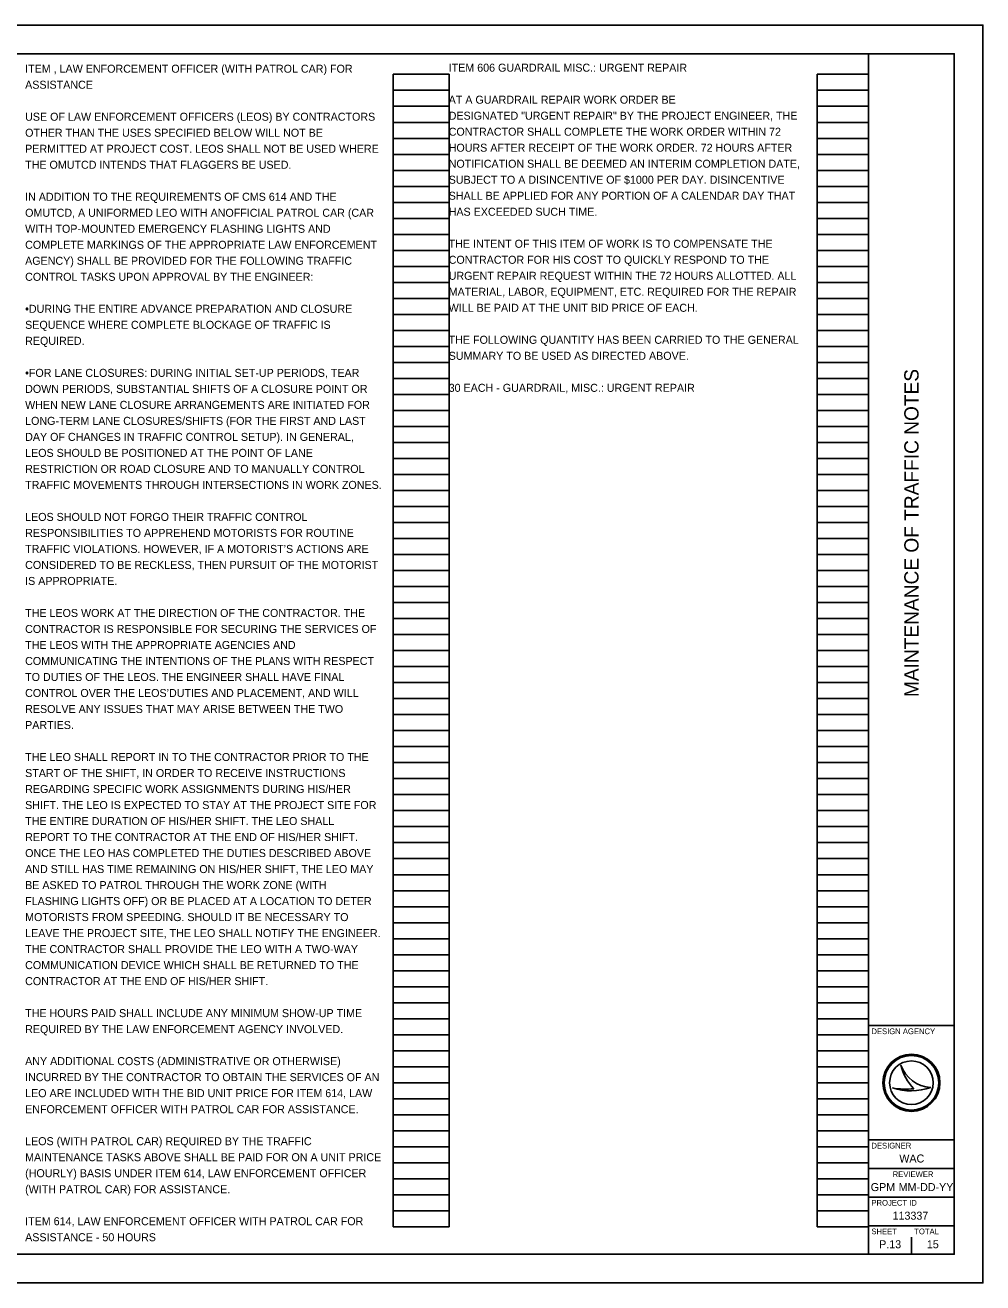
# Model space of a CAD drawing. Extents: x 0 to 34, y 0 to 22.
# Drawn here: x 17.24 to 34, y 0 to 22 of the extents above; entities that cross this region are included whole.
import ezdxf

# ---------------------------------------------------------------- set-up
doc = ezdxf.new("R2010")
doc.units = 0
for name, color, linetype in [('SH_Border', 7, 'Continuous'), ('SH_Cut_Line', 7, 'Continuous'), ('SH_Data', 7, 'Continuous'), ('SH_Text', 7, 'Continuous')]:
    doc.layers.add(name, color=color, linetype=linetype)

msp = doc.modelspace()

# ---------------------------------------------------------------- linework, layer by layer
at = {"layer": 'SH_Border'}
for p, q in [((32, 0.5), (32, 21.5)), ((32, 4.5), (33.5, 4.5)), ((32, 2.5), (33.5, 2.5)), ((32, 2), (33.5, 2)), ((32, 1.5), (33.5, 1.5)), ((32, 1), (33.5, 1))]:
    msp.add_line(p, q, dxfattribs=at)
msp.add_lwpolyline([(1.5, 21.5), (33.5, 21.5), (33.5, 0.5), (1.5, 0.5)], close=True, dxfattribs=at)
at = {"layer": 'SH_Cut_Line'}
msp.add_lwpolyline([(0, 0), (34, 0), (34, 22), (0, 22)], close=True, dxfattribs=at)
at = {"layer": 'SH_Data'}
for p, q in [((23.68, 0.98), (23.68, 21.14)), ((23.68, 21.14), (24.66, 21.14)), ((24.66, 0.98), (24.66, 21.14)), ((31.1, 0.98), (31.1, 21.14)), ((31.1, 21.14), (32, 21.14)), ((32, 0.98), (32, 21.14)), ((23.68, 20.86), (24.66, 20.86)), ((31.1, 20.86), (32, 20.86)), ((23.68, 20.58), (24.66, 20.58)), ((31.1, 20.58), (32, 20.58)), ((23.68, 20.3), (24.66, 20.3)), ((31.1, 20.3), (32, 20.3)), ((23.68, 20.02), (24.66, 20.02)), ((31.1, 20.02), (32, 20.02)), ((23.68, 19.74), (24.66, 19.74)), ((31.1, 19.74), (32, 19.74)), ((23.68, 19.46), (24.66, 19.46)), ((31.1, 19.46), (32, 19.46)), ((23.68, 19.18), (24.66, 19.18)), ((31.1, 19.18), (32, 19.18)), ((23.68, 18.9), (24.66, 18.9)), ((31.1, 18.9), (32, 18.9)), ((23.68, 18.62), (24.66, 18.62)), ((31.1, 18.62), (32, 18.62)), ((23.68, 18.34), (24.66, 18.34)), ((31.1, 18.34), (32, 18.34)), ((23.68, 18.06), (24.66, 18.06)), ((31.1, 18.06), (32, 18.06)), ((23.68, 17.78), (24.66, 17.78)), ((31.1, 17.78), (32, 17.78)), ((23.68, 17.5), (24.66, 17.5)), ((31.1, 17.5), (32, 17.5)), ((23.68, 17.22), (24.66, 17.22)), ((31.1, 17.22), (32, 17.22)), ((23.68, 16.94), (24.66, 16.94)), ((31.1, 16.94), (32, 16.94)), ((23.68, 16.66), (24.66, 16.66)), ((31.1, 16.66), (32, 16.66)), ((23.68, 16.38), (24.66, 16.38)), ((31.1, 16.38), (32, 16.38)), ((23.68, 16.1), (24.66, 16.1)), ((31.1, 16.1), (32, 16.1)), ((23.68, 15.82), (24.66, 15.82)), ((31.1, 15.82), (32, 15.82)), ((23.68, 15.54), (24.66, 15.54)), ((31.1, 15.54), (32, 15.54)), ((23.68, 15.26), (24.66, 15.26)), ((31.1, 15.26), (32, 15.26)), ((23.68, 14.98), (24.66, 14.98)), ((31.1, 14.98), (32, 14.98)), ((23.68, 14.7), (24.66, 14.7)), ((31.1, 14.7), (32, 14.7)), ((23.68, 14.42), (24.66, 14.42)), ((31.1, 14.42), (32, 14.42)), ((23.68, 14.14), (24.66, 14.14)), ((31.1, 14.14), (32, 14.14)), ((23.68, 13.86), (24.66, 13.86)), ((31.1, 13.86), (32, 13.86)), ((23.68, 13.58), (24.66, 13.58)), ((31.1, 13.58), (32, 13.58)), ((23.68, 13.3), (24.66, 13.3)), ((31.1, 13.3), (32, 13.3)), ((23.68, 13.02), (24.66, 13.02)), ((31.1, 13.02), (32, 13.02)), ((23.68, 12.74), (24.66, 12.74)), ((31.1, 12.74), (32, 12.74)), ((23.68, 12.46), (24.66, 12.46)), ((31.1, 12.46), (32, 12.46)), ((23.68, 12.18), (24.66, 12.18)), ((31.1, 12.18), (32, 12.18)), ((23.68, 11.9), (24.66, 11.9)), ((31.1, 11.9), (32, 11.9)), ((23.68, 11.62), (24.66, 11.62)), ((31.1, 11.62), (32, 11.62)), ((23.68, 11.34), (24.66, 11.34)), ((31.1, 11.34), (32, 11.34)), ((23.68, 11.06), (24.66, 11.06)), ((31.1, 11.06), (32, 11.06)), ((23.68, 10.78), (24.66, 10.78)), ((31.1, 10.78), (32, 10.78)), ((23.68, 10.5), (24.66, 10.5)), ((31.1, 10.5), (32, 10.5)), ((23.68, 10.22), (24.66, 10.22)), ((31.1, 10.22), (32, 10.22)), ((23.68, 9.94), (24.66, 9.94)), ((31.1, 9.94), (32, 9.94)), ((23.68, 9.66), (24.66, 9.66)), ((31.1, 9.66), (32, 9.66)), ((23.68, 9.38), (24.66, 9.38)), ((31.1, 9.38), (32, 9.38)), ((23.68, 9.1), (24.66, 9.1)), ((31.1, 9.1), (32, 9.1)), ((23.68, 8.82), (24.66, 8.82)), ((31.1, 8.82), (32, 8.82)), ((23.68, 8.54), (24.66, 8.54)), ((31.1, 8.54), (32, 8.54)), ((23.68, 8.26), (24.66, 8.26)), ((31.1, 8.26), (32, 8.26)), ((23.68, 7.98), (24.66, 7.98)), ((31.1, 7.98), (32, 7.98)), ((23.68, 7.7), (24.66, 7.7)), ((31.1, 7.7), (32, 7.7)), ((23.68, 7.42), (24.66, 7.42)), ((31.1, 7.42), (32, 7.42)), ((23.68, 7.14), (24.66, 7.14)), ((31.1, 7.14), (32, 7.14)), ((23.68, 6.86), (24.66, 6.86)), ((31.1, 6.86), (32, 6.86)), ((23.68, 6.58), (24.66, 6.58)), ((31.1, 6.58), (32, 6.58)), ((23.68, 6.3), (24.66, 6.3)), ((31.1, 6.3), (32, 6.3)), ((23.68, 6.02), (24.66, 6.02)), ((31.1, 6.02), (32, 6.02)), ((23.68, 5.74), (24.66, 5.74)), ((31.1, 5.74), (32, 5.74)), ((23.68, 5.46), (24.66, 5.46)), ((31.1, 5.46), (32, 5.46)), ((23.68, 5.18), (24.66, 5.18)), ((31.1, 5.18), (32, 5.18)), ((23.68, 4.9), (24.66, 4.9)), ((31.1, 4.9), (32, 4.9)), ((23.68, 4.62), (24.66, 4.62)), ((31.1, 4.62), (32, 4.62)), ((23.68, 4.34), (24.66, 4.34)), ((31.1, 4.34), (32, 4.34)), ((23.68, 4.06), (24.66, 4.06)), ((31.1, 4.06), (32, 4.06)), ((23.68, 3.78), (24.66, 3.78)), ((31.1, 3.78), (32, 3.78)), ((32.567, 3.81), (32.567, 3.81)), ((23.68, 3.5), (24.66, 3.5)), ((31.1, 3.5), (32, 3.5)), ((32.417, 3.41), (32.417, 3.41)), ((32.75, 3.5), (32.75, 3.5)), ((33.087, 3.419), (33.087, 3.419)), ((23.68, 3.22), (24.66, 3.22)), ((31.1, 3.22), (32, 3.22)), ((23.68, 2.94), (24.66, 2.94)), ((31.1, 2.94), (32, 2.94)), ((23.68, 2.66), (24.66, 2.66)), ((31.1, 2.66), (32, 2.66)), ((23.68, 2.38), (24.66, 2.38)), ((31.1, 2.38), (32, 2.38)), ((23.68, 2.1), (24.66, 2.1)), ((31.1, 2.1), (32, 2.1)), ((23.68, 1.82), (24.66, 1.82)), ((31.1, 1.82), (32, 1.82)), ((23.68, 1.54), (24.66, 1.54)), ((31.1, 1.54), (32, 1.54)), ((23.68, 1.26), (24.66, 1.26)), ((31.1, 1.26), (32, 1.26)), ((23.68, 0.98), (24.66, 0.98)), ((31.1, 0.98), (32, 0.98)), ((32.375, 0.675), (32.375, 0.675)), ((32.75, 0.5), (32.75, 0.8))]:
    msp.add_line(p, q, dxfattribs=at)
for radius in [0.5, 0.477, 0.477, 0.382]:
    msp.add_circle((32.75, 3.5), radius, dxfattribs=at)
for centre, radius, start, end in [((33.116, 3.998), 0.58, 198.9257, 198.9319), ((33.347, 3.97), 0.796, 191.6379, 191.6421), ((33.116, 3.998), 0.58, 198.9319, 267.1657), ((33.347, 3.97), 0.796, 191.6421, 226.0947), ((32.739, 4.37), 1.013, 251.4576, 290.0832), ((32.648, 4.654), 1.266, 259.4964, 259.4995), ((32.739, 4.37), 1.013, 251.4527, 251.4576), ((32.648, 4.654), 1.266, 259.4995, 276.6672)]:
    msp.add_arc(centre, radius, start, end, dxfattribs=at)

# ---------------------------------------------------------------- texts
msp.add_text('MAINTENANCE OF TRAFFIC NOTES', height=0.25, rotation=90, dxfattribs=at).set_placement((32.875, 10.247))
for s, height, p in [('DESIGN AGENCY', 0.1, (32.05, 4.35)), ('DESIGNER', 0.1, (32.05, 2.35)), ('WAC', 0.14, (32.538, 2.105)), ('REVIEWER', 0.1, (32.422, 1.85)), ('GPM', 0.14, (32.038, 1.605)), ('MM-DD-YY', 0.14, (32.527, 1.605)), ('PROJECT ID', 0.1, (32.05, 1.35)), ('113337', 0.14, (32.42, 1.105)), ('SHEET', 0.1, (32.05, 0.85)), ('TOTAL', 0.1, (32.8, 0.85)), ('P.13', 0.14, (32.185, 0.605)), ('15', 0.14, (33.02, 0.605))]:
    msp.add_text(s, height=height, dxfattribs=at).set_placement(p)
at = {"layer": 'SH_Text'}
for s, p in [('ITEM , LAW ENFORCEMENT OFFICER (WITH PATROL CAR) FOR', (17.24, 21.168)), ('ITEM 606 GUARDRAIL MISC.: URGENT REPAIR', (24.652, 21.186)), ('ASSISTANCE', (17.24, 20.888)), ('AT A GUARDRAIL REPAIR WORK ORDER BE', (24.652, 20.626)), ('USE OF LAW ENFORCEMENT OFFICERS (LEOS) BY CONTRACTORS', (17.24, 20.328)), ('DESIGNATED "URGENT REPAIR" BY THE PROJECT ENGINEER, THE', (24.652, 20.346)), ('OTHER THAN THE USES SPECIFIED BELOW WILL NOT BE', (17.24, 20.048)), ('CONTRACTOR SHALL COMPLETE THE WORK ORDER WITHIN 72', (24.652, 20.066)), ('PERMITTED AT PROJECT COST. LEOS SHALL NOT BE USED WHERE', (17.24, 19.768)), ('HOURS AFTER RECEIPT OF THE WORK ORDER. 72 HOURS AFTER', (24.652, 19.786)), ('THE OMUTCD INTENDS THAT FLAGGERS BE USED.', (17.24, 19.488)), ('NOTIFICATION SHALL BE DEEMED AN INTERIM COMPLETION DATE,', (24.652, 19.506)), ('SUBJECT TO A DISINCENTIVE OF $1000 PER DAY. DISINCENTIVE', (24.652, 19.226)), ('IN ADDITION TO THE REQUIREMENTS OF CMS 614 AND THE', (17.24, 18.928)), ('SHALL BE APPLIED FOR ANY PORTION OF A CALENDAR DAY THAT', (24.652, 18.946)), ('OMUTCD, A UNIFORMED LEO WITH ANOFFICIAL PATROL CAR (CAR', (17.24, 18.648)), ('HAS EXCEEDED SUCH TIME.', (24.652, 18.666)), ('WITH TOP-MOUNTED EMERGENCY FLASHING LIGHTS AND', (17.24, 18.368)), ('COMPLETE MARKINGS OF THE APPROPRIATE LAW ENFORCEMENT', (17.24, 18.088)), ('THE INTENT OF THIS ITEM OF WORK IS TO COMPENSATE THE', (24.652, 18.106)), ('AGENCY) SHALL BE PROVIDED FOR THE FOLLOWING TRAFFIC', (17.24, 17.808)), ('CONTRACTOR FOR HIS COST TO QUICKLY RESPOND TO THE', (24.652, 17.826)), ('CONTROL TASKS UPON APPROVAL BY THE ENGINEER:', (17.24, 17.528)), ('URGENT REPAIR REQUEST WITHIN THE 72 HOURS ALLOTTED. ALL', (24.652, 17.546)), ('MATERIAL, LABOR, EQUIPMENT, ETC. REQUIRED FOR THE REPAIR', (24.652, 17.266)), ('•DURING THE ENTIRE ADVANCE PREPARATION AND CLOSURE', (17.24, 16.968)), ('WILL BE PAID AT THE UNIT BID PRICE OF EACH.', (24.652, 16.986)), ('SEQUENCE WHERE COMPLETE BLOCKAGE OF TRAFFIC IS', (17.24, 16.688)), ('REQUIRED.', (17.24, 16.408)), ('THE FOLLOWING QUANTITY HAS BEEN CARRIED TO THE GENERAL', (24.652, 16.426)), ('SUMMARY TO BE USED AS DIRECTED ABOVE.', (24.652, 16.146)), ('•FOR LANE CLOSURES: DURING INITIAL SET-UP PERIODS, TEAR', (17.24, 15.848)), ('DOWN PERIODS, SUBSTANTIAL SHIFTS OF A CLOSURE POINT OR', (17.24, 15.568)), ('30 EACH - GUARDRAIL, MISC.: URGENT REPAIR', (24.652, 15.586)), ('WHEN NEW LANE CLOSURE ARRANGEMENTS ARE INITIATED FOR', (17.24, 15.288)), ('LONG-TERM LANE CLOSURES/SHIFTS (FOR THE FIRST AND LAST', (17.24, 15.008)), ('DAY OF CHANGES IN TRAFFIC CONTROL SETUP). IN GENERAL,', (17.24, 14.728)), ('LEOS SHOULD BE POSITIONED AT THE POINT OF LANE', (17.24, 14.448)), ('RESTRICTION OR ROAD CLOSURE AND TO MANUALLY CONTROL', (17.24, 14.168)), ('TRAFFIC MOVEMENTS THROUGH INTERSECTIONS IN WORK ZONES.', (17.24, 13.888)), ('LEOS SHOULD NOT FORGO THEIR TRAFFIC CONTROL', (17.24, 13.328)), ('RESPONSIBILITIES TO APPREHEND MOTORISTS FOR ROUTINE', (17.24, 13.048)), ('TRAFFIC VIOLATIONS. HOWEVER, IF A MOTORIST’S ACTIONS ARE', (17.24, 12.768)), ('CONSIDERED TO BE RECKLESS, THEN PURSUIT OF THE MOTORIST', (17.24, 12.488)), ('IS APPROPRIATE.', (17.24, 12.208)), ('THE LEOS WORK AT THE DIRECTION OF THE CONTRACTOR. THE', (17.24, 11.648)), ('CONTRACTOR IS RESPONSIBLE FOR SECURING THE SERVICES OF', (17.24, 11.368)), ('THE LEOS WITH THE APPROPRIATE AGENCIES AND', (17.24, 11.088)), ('COMMUNICATING THE INTENTIONS OF THE PLANS WITH RESPECT', (17.24, 10.808)), ('TO DUTIES OF THE LEOS. THE ENGINEER SHALL HAVE FINAL', (17.24, 10.528)), ('CONTROL OVER THE LEOS’DUTIES AND PLACEMENT, AND WILL', (17.24, 10.248)), ('RESOLVE ANY ISSUES THAT MAY ARISE BETWEEN THE TWO', (17.24, 9.968)), ('PARTIES.', (17.24, 9.688)), ('THE LEO SHALL REPORT IN TO THE CONTRACTOR PRIOR TO THE', (17.24, 9.128)), ('START OF THE SHIFT, IN ORDER TO RECEIVE INSTRUCTIONS', (17.24, 8.848)), ('REGARDING SPECIFIC WORK ASSIGNMENTS DURING HIS/HER', (17.24, 8.568)), ('SHIFT. THE LEO IS EXPECTED TO STAY AT THE PROJECT SITE FOR', (17.24, 8.288)), ('THE ENTIRE DURATION OF HIS/HER SHIFT. THE LEO SHALL', (17.24, 8.008)), ('REPORT TO THE CONTRACTOR AT THE END OF HIS/HER SHIFT.', (17.24, 7.728)), ('ONCE THE LEO HAS COMPLETED THE DUTIES DESCRIBED ABOVE', (17.24, 7.448)), ('AND STILL HAS TIME REMAINING ON HIS/HER SHIFT, THE LEO MAY', (17.24, 7.168)), ('BE ASKED TO PATROL THROUGH THE WORK ZONE (WITH', (17.24, 6.888)), ('FLASHING LIGHTS OFF) OR BE PLACED AT A LOCATION TO DETER', (17.24, 6.608)), ('MOTORISTS FROM SPEEDING. SHOULD IT BE NECESSARY TO', (17.24, 6.328)), ('LEAVE THE PROJECT SITE, THE LEO SHALL NOTIFY THE ENGINEER.', (17.24, 6.048)), ('THE CONTRACTOR SHALL PROVIDE THE LEO WITH A TWO-WAY', (17.24, 5.768)), ('COMMUNICATION DEVICE WHICH SHALL BE RETURNED TO THE', (17.24, 5.488)), ('CONTRACTOR AT THE END OF HIS/HER SHIFT.', (17.24, 5.208)), ('THE HOURS PAID SHALL INCLUDE ANY MINIMUM SHOW-UP TIME', (17.24, 4.648)), ('REQUIRED BY THE LAW ENFORCEMENT AGENCY INVOLVED.', (17.24, 4.368)), ('ANY ADDITIONAL COSTS (ADMINISTRATIVE OR OTHERWISE)', (17.24, 3.808)), ('INCURRED BY THE CONTRACTOR TO OBTAIN THE SERVICES OF AN', (17.24, 3.528)), ('LEO ARE INCLUDED WITH THE BID UNIT PRICE FOR ITEM 614, LAW', (17.24, 3.248)), ('ENFORCEMENT OFFICER WITH PATROL CAR FOR ASSISTANCE.', (17.24, 2.968)), ('LEOS (WITH PATROL CAR) REQUIRED BY THE TRAFFIC', (17.24, 2.408)), ('MAINTENANCE TASKS ABOVE SHALL BE PAID FOR ON A UNIT PRICE', (17.24, 2.128)), ('(HOURLY) BASIS UNDER ITEM 614, LAW ENFORCEMENT OFFICER', (17.24, 1.848)), ('(WITH PATROL CAR) FOR ASSISTANCE.', (17.24, 1.568)), ('ITEM 614, LAW ENFORCEMENT OFFICER WITH PATROL CAR FOR', (17.24, 1.008)), ('ASSISTANCE - 50 HOURS', (17.24, 0.728))]:
    msp.add_text(s, height=0.14, dxfattribs=at).set_placement(p)

doc.saveas('drawing.dxf')
